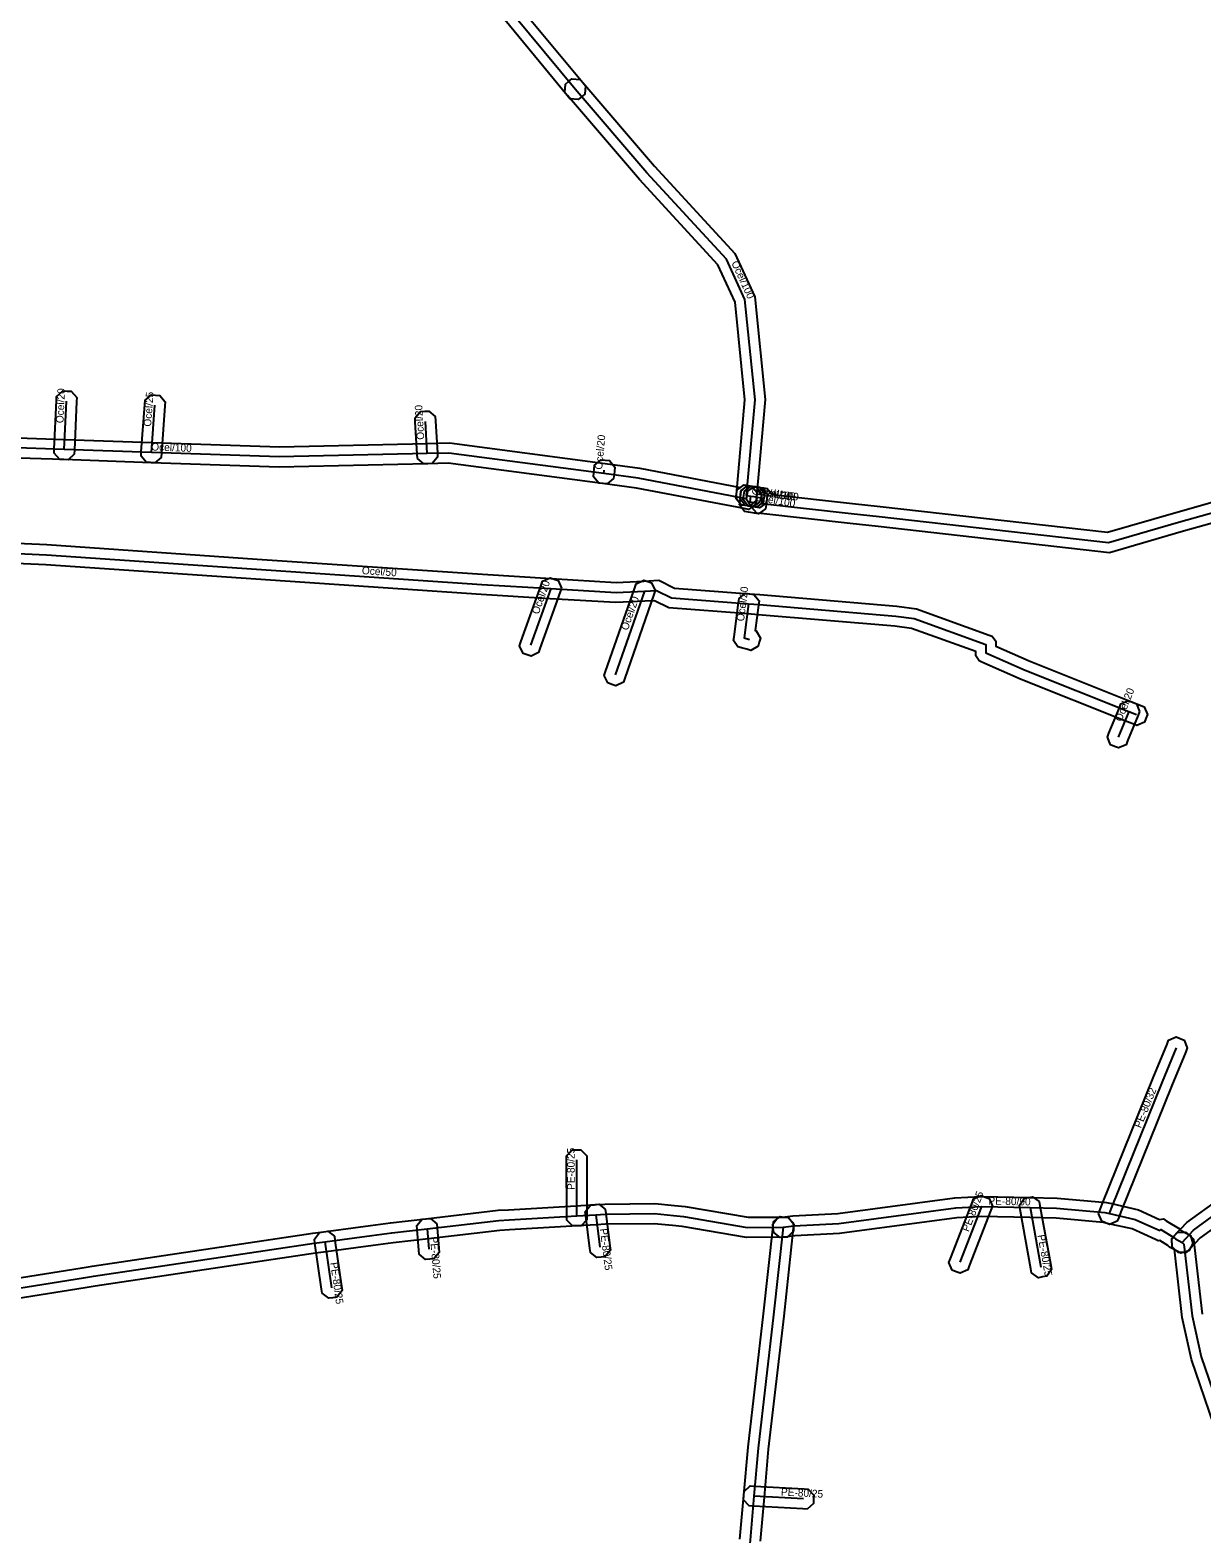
# Model space of a CAD drawing. Extents: x -569373 to -565022, y -1135090 to -1131496.
# Drawn here: x -565803.8 to -565687.7, y -1133883.9 to -1133734.9 of the extents above; entities that cross this region are included whole.
import ezdxf

# ---------------------------------------------------------------- set-up
doc = ezdxf.new("R2010")
doc.units = 0
for name, color, linetype in [('1', 7, 'Continuous'), ('24', 7, 'Continuous'), ('30', 7, 'Continuous')]:
    doc.layers.add(name, color=color, linetype=linetype)

msp = doc.modelspace()

# ---------------------------------------------------------------- linework, layer by layer
at = {"layer": '1'}
for points in [[(-565755.962, -1133731.747), (-565749.03, -1133740.122), (-565748.766, -1133740.441), (-565748.843, -1133741.266), (-565749.162, -1133741.53), (-565749.481, -1133741.794), (-565750.306, -1133741.717), (-565750.57, -1133741.398), (-565758.16, -1133732.228)], [(-565805.939, -1133775.27), (-565800.346, -1133775.461), (-565791.726, -1133775.761), (-565779.084, -1133776.19), (-565764.463, -1133775.86), (-565762.246, -1133775.808), (-565746.809, -1133777.839), (-565743.39, -1133778.292), (-565733.424, -1133780.205), (-565733.117, -1133779.967), (-565732.706, -1133780.018), (-565732.295, -1133780.069), (-565731.787, -1133780.723), (-565731.838, -1133781.134), (-565731.878, -1133781.454), (-565731.931, -1133781.884), (-565732.282, -1133782.139), (-565732.633, -1133782.394), (-565733.059, -1133782.312), (-565743.71, -1133780.268), (-565747.071, -1133779.821), (-565762.354, -1133777.812), (-565764.417, -1133777.86), (-565779.096, -1133778.19), (-565791.794, -1133777.759), (-565800.414, -1133777.459), (-565806.001, -1133777.27)], [(-565683.638, -1133782.882), (-565689.775, -1133784.611), (-565696.894, -1133786.676), (-565719.8, -1133784.084), (-565722.56, -1133783.784), (-565731.421, -1133782.794), (-565731.801, -1133782.751), (-565732.31, -1133782.182), (-565732.31, -1133782.097), (-565732.363, -1133782.088), (-565732.844, -1133781.414), (-565732.776, -1133781.006), (-565732.708, -1133780.597), (-565732.034, -1133780.116), (-565731.626, -1133780.184), (-565731.146, -1133780.264), (-565730.784, -1133780.324), (-565730.31, -1133780.883), (-565730.31, -1133780.905), (-565722.34, -1133781.796), (-565719.58, -1133782.096), (-565697.066, -1133784.644), (-565690.325, -1133782.689), (-565684.182, -1133780.958)], [(-565821.436, -1133785.008), (-565802.103, -1133785.872), (-565781.272, -1133787.302), (-565758.965, -1133788.812), (-565752.159, -1133789.232), (-565745.745, -1133789.618), (-565742.99, -1133789.481), (-565741.519, -1133789.408), (-565739.97, -1133790.178), (-565732.554, -1133790.743), (-565731.5, -1133790.823), (-565717.934, -1133791.975), (-565716.004, -1133792.222), (-565708.79, -1133794.83), (-565708.496, -1133794.936), (-565708.134, -1133795.445), (-565708.13, -1133795.758), (-565708.128, -1133795.937), (-565704.842, -1133797.398), (-565694.61, -1133801.471), (-565693.831, -1133801.781), (-565693.446, -1133801.934), (-565693.118, -1133802.694), (-565693.271, -1133803.079), (-565693.424, -1133803.464), (-565694.184, -1133803.792), (-565694.569, -1133803.639), (-565695.35, -1133803.329), (-565705.618, -1133799.242), (-565709.526, -1133797.504), (-565709.794, -1133797.385), (-565710.116, -1133796.895), (-565710.12, -1133796.602), (-565710.121, -1133796.475), (-565716.476, -1133794.178), (-565718.146, -1133793.965), (-565731.66, -1133792.817), (-565732.706, -1133792.737), (-565740.51, -1133792.142), (-565741.941, -1133791.432), (-565742.89, -1133791.479), (-565745.755, -1133791.622), (-565752.281, -1133791.228), (-565759.095, -1133790.808), (-565781.408, -1133789.298), (-565802.217, -1133787.868), (-565821.404, -1133787.012)], [(-565684.684, -1133852.193), (-565687.896, -1133854.514), (-565688.969, -1133855.663), (-565689.252, -1133855.965), (-565690.08, -1133855.993), (-565690.383, -1133855.711), (-565690.685, -1133855.428), (-565690.713, -1133854.6), (-565690.431, -1133854.297), (-565689.224, -1133853.006), (-565686.016, -1133850.687)], [(-565810.668, -1133859.412), (-565798.624, -1133857.492), (-565797.629, -1133857.341), (-565775.779, -1133854.08), (-565774.701, -1133853.939), (-565770.052, -1133853.315), (-565768.065, -1133853.048), (-565764.566, -1133852.637), (-565757.428, -1133851.803), (-565756.399, -1133851.742), (-565749.688, -1133851.352), (-565747.811, -1133851.242), (-565746.857, -1133851.18), (-565741.893, -1133851.129), (-565739.947, -1133851.331), (-565738.915, -1133851.439), (-565732.669, -1133852.49), (-565729.196, -1133852.47), (-565728.782, -1133852.468), (-565728.192, -1133853.05), (-565728.19, -1133853.464), (-565728.188, -1133853.878), (-565728.77, -1133854.468), (-565729.184, -1133854.47), (-565732.831, -1133854.49), (-565739.185, -1133853.421), (-565740.153, -1133853.321), (-565741.987, -1133853.131), (-565746.783, -1133853.18), (-565747.689, -1133853.238), (-565749.572, -1133853.348), (-565756.281, -1133853.738), (-565757.252, -1133853.797), (-565764.334, -1133854.623), (-565767.815, -1133855.032), (-565769.786, -1133855.297), (-565774.439, -1133855.921), (-565775.501, -1133856.06), (-565797.331, -1133859.319), (-565798.316, -1133859.468), (-565810.352, -1133861.388)], [(-565733.476, -1133884.381), (-565733.086, -1133880.021), (-565732.665, -1133875.268), (-565731.134, -1133862.058), (-565730.184, -1133853.361), (-565730.139, -1133852.949), (-565729.493, -1133852.431), (-565729.081, -1133852.476), (-565728.669, -1133852.521), (-565728.151, -1133853.167), (-565728.196, -1133853.579), (-565729.146, -1133862.282), (-565730.675, -1133875.472), (-565731.094, -1133880.199), (-565731.484, -1133884.559)], [(-565685.698, -1133875.567), (-565688.754, -1133866.571), (-565689.687, -1133862.427), (-565690.461, -1133855.641), (-565690.676, -1133855.449), (-565690.721, -1133854.622), (-565690.445, -1133854.313), (-565690.169, -1133854.004), (-565689.342, -1133853.959), (-565689.033, -1133854.235), (-565688.56, -1133854.659), (-565687.713, -1133862.093)]]:
    msp.add_lwpolyline(points, dxfattribs=at)
for points in [[(-565733.863, -1133781.334), (-565733.826, -1133780.921), (-565732.985, -1133771.526), (-565733.958, -1133761.865), (-565735.653, -1133758.151), (-565743.437, -1133749.715), (-565750.559, -1133741.411), (-565750.829, -1133741.097), (-565750.765, -1133740.271), (-565750.451, -1133740.001), (-565750.137, -1133739.731), (-565749.311, -1133739.795), (-565749.041, -1133740.109), (-565741.943, -1133748.385), (-565733.967, -1133757.029), (-565732.002, -1133761.335), (-565730.975, -1133771.514), (-565731.834, -1133781.099), (-565731.871, -1133781.512), (-565732.506, -1133782.043), (-565732.919, -1133782.006), (-565733.332, -1133781.969)], [(-565801.398, -1133776.828), (-565801.379, -1133776.414), (-565801.159, -1133771.614), (-565801.14, -1133771.2), (-565800.528, -1133770.642), (-565800.114, -1133770.661), (-565799.7, -1133770.68), (-565799.142, -1133771.292), (-565799.161, -1133771.706), (-565799.381, -1133776.506), (-565799.4, -1133776.92), (-565800.012, -1133777.478), (-565800.426, -1133777.459), (-565800.84, -1133777.44)], [(-565792.787, -1133777.101), (-565792.757, -1133776.688), (-565792.417, -1133771.988), (-565792.387, -1133771.575), (-565791.761, -1133771.033), (-565791.348, -1133771.063), (-565790.935, -1133771.093), (-565790.393, -1133771.719), (-565790.423, -1133772.132), (-565790.763, -1133776.832), (-565790.793, -1133777.245), (-565791.419, -1133777.787), (-565791.832, -1133777.757), (-565792.245, -1133777.727)], [(-565765.414, -1133777.333), (-565765.438, -1133776.919), (-565765.628, -1133773.729), (-565765.653, -1133773.316), (-565765.103, -1133772.696), (-565764.689, -1133772.672), (-565764.276, -1133772.647), (-565763.656, -1133773.197), (-565763.632, -1133773.611), (-565763.442, -1133776.801), (-565763.417, -1133777.214), (-565763.967, -1133777.834), (-565764.381, -1133777.858), (-565764.794, -1133777.883)], [(-565747.975, -1133779.149), (-565747.936, -1133778.737), (-565747.906, -1133778.417), (-565747.867, -1133778.004), (-565747.229, -1133777.475), (-565746.817, -1133777.514), (-565746.404, -1133777.553), (-565745.875, -1133778.191), (-565745.914, -1133778.603), (-565745.944, -1133778.923), (-565745.983, -1133779.336), (-565746.621, -1133779.865), (-565747.033, -1133779.826), (-565747.446, -1133779.787)], [(-565733.074, -1133779.956), (-565732.666, -1133780.024), (-565732.246, -1133780.094), (-565731.837, -1133780.162), (-565731.356, -1133780.836), (-565731.424, -1133781.244), (-565731.492, -1133781.653), (-565732.166, -1133782.134), (-565732.574, -1133782.066), (-565732.994, -1133781.996), (-565733.403, -1133781.928), (-565733.884, -1133781.254), (-565733.816, -1133780.846), (-565733.748, -1133780.437)], [(-565731.92, -1133780.115), (-565731.896, -1133780.143), (-565731.642, -1133780.181), (-565731.232, -1133780.242), (-565730.74, -1133780.908), (-565730.801, -1133781.318), (-565730.891, -1133781.918), (-565730.953, -1133782.333), (-565731.293, -1133782.58), (-565731.633, -1133782.826), (-565732.047, -1133782.756), (-565732.637, -1133782.656), (-565733.032, -1133782.589), (-565733.511, -1133781.948), (-565733.463, -1133781.55), (-565733.425, -1133781.241), (-565733.407, -1133781.003), (-565733.375, -1133780.59), (-565732.746, -1133780.051), (-565732.333, -1133780.083)], [(-565732.676, -1133780.031), (-565732.266, -1133780.09), (-565731.956, -1133780.135), (-565731.546, -1133780.195), (-565731.051, -1133780.859), (-565731.11, -1133781.269), (-565731.17, -1133781.679), (-565731.834, -1133782.174), (-565732.244, -1133782.115), (-565732.554, -1133782.07), (-565732.964, -1133782.01), (-565733.459, -1133781.346), (-565733.4, -1133780.936), (-565733.34, -1133780.526)], [(-565732.366, -1133780.076), (-565731.956, -1133780.135), (-565731.646, -1133780.18), (-565731.236, -1133780.24), (-565730.741, -1133780.904), (-565730.8, -1133781.314), (-565730.86, -1133781.724), (-565731.524, -1133782.219), (-565731.934, -1133782.16), (-565732.244, -1133782.115), (-565732.654, -1133782.055), (-565733.149, -1133781.391), (-565733.09, -1133780.981), (-565733.03, -1133780.571)], [(-565751.139, -1133790.176), (-565751.278, -1133790.566), (-565753.278, -1133796.176), (-565753.417, -1133796.566), (-565754.166, -1133796.921), (-565754.556, -1133796.782), (-565754.946, -1133796.643), (-565755.301, -1133795.894), (-565755.162, -1133795.504), (-565753.162, -1133789.894), (-565753.023, -1133789.504), (-565752.274, -1133789.149), (-565751.884, -1133789.288), (-565751.494, -1133789.427)], [(-565741.86, -1133790.418), (-565741.996, -1133790.809), (-565744.886, -1133799.099), (-565745.022, -1133799.49), (-565745.768, -1133799.85), (-565746.159, -1133799.714), (-565746.55, -1133799.578), (-565746.91, -1133798.832), (-565746.774, -1133798.441), (-565743.884, -1133790.151), (-565743.748, -1133789.76), (-565743.002, -1133789.4), (-565742.611, -1133789.536), (-565742.22, -1133789.672)], [(-565731.638, -1133791.869), (-565731.966, -1133794.388), (-565731.863, -1133794.417), (-565731.455, -1133795.139), (-565731.566, -1133795.538), (-565731.677, -1133795.937), (-565732.399, -1133796.345), (-565732.798, -1133796.234), (-565733.338, -1133796.084), (-565733.698, -1133795.984), (-565734.11, -1133795.361), (-565734.062, -1133794.991), (-565733.622, -1133791.611), (-565733.569, -1133791.2), (-565732.912, -1133790.695), (-565732.501, -1133790.748), (-565732.09, -1133790.801), (-565731.585, -1133791.458)], [(-565693.898, -1133802.393), (-565694.054, -1133802.777), (-565695.084, -1133805.307), (-565695.24, -1133805.691), (-565696.003, -1133806.012), (-565696.387, -1133805.856), (-565696.771, -1133805.7), (-565697.092, -1133804.937), (-565696.936, -1133804.553), (-565695.906, -1133802.023), (-565695.75, -1133801.639), (-565694.987, -1133801.318), (-565694.603, -1133801.474), (-565694.219, -1133801.63)], [(-565697.973, -1133852.119), (-565697.814, -1133851.737), (-565697.596, -1133851.211), (-565692.547, -1133838.695), (-565691.187, -1133835.344), (-565691.031, -1133834.96), (-565690.268, -1133834.637), (-565689.884, -1133834.793), (-565689.5, -1133834.949), (-565689.177, -1133835.712), (-565689.333, -1133836.096), (-565690.693, -1133839.445), (-565695.744, -1133851.969), (-565695.966, -1133852.503), (-565696.125, -1133852.886), (-565696.891, -1133853.203), (-565697.273, -1133853.044), (-565697.656, -1133852.885)], [(-565750.629, -1133852.766), (-565750.63, -1133852.352), (-565750.64, -1133846.822), (-565750.641, -1133846.408), (-565750.056, -1133845.821), (-565749.642, -1133845.82), (-565749.228, -1133845.819), (-565748.641, -1133846.404), (-565748.64, -1133846.818), (-565748.63, -1133852.348), (-565748.629, -1133852.762), (-565749.214, -1133853.349), (-565749.628, -1133853.35), (-565750.042, -1133853.351)], [(-565704.773, -1133852.53), (-565709.563, -1133852.42), (-565711.996, -1133852.556), (-565723.607, -1133854.106), (-565728.056, -1133854.347), (-565729.076, -1133854.464), (-565729.488, -1133854.511), (-565730.137, -1133853.995), (-565730.184, -1133853.584), (-565730.231, -1133853.172), (-565729.715, -1133852.523), (-565729.304, -1133852.476), (-565728.224, -1133852.353), (-565723.793, -1133852.114), (-565712.184, -1133850.564), (-565709.608, -1133850.42), (-565709.549, -1133850.42), (-565704.727, -1133850.53), (-565702.064, -1133850.591), (-565697.174, -1133851.03), (-565696.669, -1133851.145), (-565694.009, -1133851.747), (-565691.919, -1133852.698), (-565691.55, -1133852.663), (-565691.265, -1133852.839), (-565689.9, -1133853.681), (-565689.77, -1133853.803), (-565689.221, -1133854.102), (-565688.857, -1133854.3), (-565688.624, -1133855.095), (-565688.822, -1133855.459), (-565689.02, -1133855.823), (-565689.815, -1133856.056), (-565690.179, -1133855.858), (-565690.95, -1133855.437), (-565691.12, -1133855.279), (-565691.882, -1133854.808), (-565692.05, -1133854.835), (-565692.324, -1133854.71), (-565694.651, -1133853.653), (-565697.111, -1133853.095), (-565697.486, -1133853.01), (-565702.176, -1133852.589)], [(-565708.477, -1133851.395), (-565708.627, -1133851.781), (-565710.767, -1133857.311), (-565710.917, -1133857.697), (-565711.675, -1133858.033), (-565712.061, -1133857.883), (-565712.447, -1133857.733), (-565712.783, -1133856.975), (-565712.633, -1133856.589), (-565710.493, -1133851.059), (-565710.343, -1133850.673), (-565709.585, -1133850.337), (-565709.199, -1133850.487), (-565708.813, -1133850.637)], [(-565703.84, -1133850.943), (-565703.766, -1133851.351), (-565702.696, -1133857.241), (-565702.622, -1133857.649), (-565703.093, -1133858.33), (-565703.501, -1133858.404), (-565703.909, -1133858.478), (-565704.59, -1133858.007), (-565704.664, -1133857.599), (-565705.734, -1133851.709), (-565705.808, -1133851.301), (-565705.337, -1133850.62), (-565704.929, -1133850.546), (-565704.521, -1133850.472)], [(-565746.809, -1133851.705), (-565746.758, -1133852.116), (-565746.358, -1133855.326), (-565746.307, -1133855.737), (-565746.815, -1133856.391), (-565747.226, -1133856.442), (-565747.637, -1133856.493), (-565748.291, -1133855.985), (-565748.342, -1133855.574), (-565748.742, -1133852.364), (-565748.793, -1133851.953), (-565748.285, -1133851.299), (-565747.874, -1133851.248), (-565747.463, -1133851.197)], [(-565763.488, -1133853.133), (-565763.454, -1133853.546), (-565763.284, -1133855.566), (-565763.249, -1133855.979), (-565763.783, -1133856.612), (-565764.196, -1133856.646), (-565764.609, -1133856.681), (-565765.242, -1133856.147), (-565765.276, -1133855.734), (-565765.446, -1133853.714), (-565765.481, -1133853.301), (-565764.947, -1133852.668), (-565764.534, -1133852.634), (-565764.121, -1133852.599)], [(-565773.638, -1133854.38), (-565773.58, -1133854.79), (-565772.94, -1133859.33), (-565772.882, -1133859.74), (-565773.38, -1133860.402), (-565773.79, -1133860.46), (-565774.2, -1133860.518), (-565774.862, -1133860.02), (-565774.92, -1133859.61), (-565775.56, -1133855.07), (-565775.618, -1133854.66), (-565775.12, -1133853.998), (-565774.71, -1133853.94), (-565774.3, -1133853.882)], [(-565726.821, -1133881.401), (-565727.235, -1133881.378), (-565732.145, -1133881.108), (-565732.558, -1133881.086), (-565733.111, -1133880.469), (-565733.088, -1133880.055), (-565733.066, -1133879.642), (-565732.449, -1133879.089), (-565732.035, -1133879.112), (-565727.125, -1133879.382), (-565726.712, -1133879.404), (-565726.159, -1133880.021), (-565726.182, -1133880.435), (-565726.204, -1133880.848)]]:
    msp.add_lwpolyline(points, close=True, dxfattribs=at)
at = {"layer": '24'}
for points in [[(-565749.8, -1133740.76), (-565757.39, -1133731.59), (-565753.04, -1133728.21), (-565757.57, -1133717.97), (-565761.42, -1133709.27), (-565765.12, -1133697), (-565767.29, -1133689.8), (-565770.57, -1133673.93), (-565771.29, -1133668.81), (-565774.1, -1133648.7), (-565774.91, -1133640.21)], [(-565732.83, -1133781.01), (-565731.98, -1133771.52), (-565732.98, -1133761.6), (-565734.81, -1133757.59), (-565742.69, -1133749.05), (-565749.8, -1133740.76)], [(-565800.38, -1133776.46), (-565800.16, -1133771.66)], [(-565731.79, -1133781.17), (-565731.31, -1133781.25), (-565731.31, -1133781.8), (-565722.45, -1133782.79), (-565719.69, -1133783.09), (-565696.98, -1133785.66), (-565690.05, -1133783.65), (-565683.91, -1133781.92), (-565674.33, -1133779.21), (-565666.38, -1133776.92), (-565664.06, -1133776.24), (-565646.12, -1133770.95), (-565644.96, -1133770.62), (-565644.79, -1133770.7), (-565643.12, -1133776.29), (-565639.22, -1133790.9), (-565637.82, -1133792.15), (-565630.96, -1133797.98), (-565630.6, -1133798.24), (-565626.94, -1133796.32), (-565610.38, -1133787.45)], [(-565791.76, -1133776.76), (-565791.42, -1133772.06)], [(-565764.44, -1133776.86), (-565764.63, -1133773.67)], [(-565732.83, -1133781.01), (-565732.87, -1133781.33), (-565743.55, -1133779.28), (-565746.94, -1133778.83), (-565762.3, -1133776.81), (-565764.44, -1133776.86), (-565779.09, -1133777.19), (-565791.76, -1133776.76), (-565800.38, -1133776.46), (-565805.97, -1133776.27), (-565827.93, -1133775.65), (-565851.65, -1133776.72)], [(-565746.94, -1133778.83), (-565746.91, -1133778.51)], [(-565732.83, -1133781.01), (-565732.41, -1133781.08)], [(-565731.79, -1133781.17), (-565731.88, -1133781.77), (-565732.47, -1133781.67), (-565732.43, -1133781.34), (-565732.41, -1133781.08)], [(-565732.41, -1133781.08), (-565732.1, -1133781.125)], [(-565732.1, -1133781.125), (-565731.79, -1133781.17)], [(-565850.78, -1133788.29), (-565821.42, -1133786.01), (-565802.16, -1133786.87), (-565781.34, -1133788.3), (-565759.03, -1133789.81), (-565752.22, -1133790.23), (-565745.75, -1133790.62), (-565742.94, -1133790.48), (-565741.73, -1133790.42), (-565740.24, -1133791.16), (-565732.63, -1133791.74), (-565731.58, -1133791.82), (-565718.04, -1133792.97), (-565716.24, -1133793.2), (-565709.13, -1133795.77), (-565709.12, -1133796.59), (-565705.23, -1133798.32), (-565694.98, -1133802.4), (-565694.2, -1133802.71)], [(-565752.22, -1133790.23), (-565754.22, -1133795.84)], [(-565742.94, -1133790.48), (-565745.83, -1133798.77)], [(-565732.63, -1133791.74), (-565733.07, -1133795.12), (-565732.53, -1133795.27)], [(-565694.98, -1133802.4), (-565696.01, -1133804.93)], [(-565689.7, -1133854.98), (-565688.56, -1133853.76), (-565685.35, -1133851.44), (-565682.29, -1133848.14), (-565672.318, -1133835.092), (-565671.59, -1133834.14), (-565658.14, -1133816.52), (-565652.84, -1133820.6), (-565648.38, -1133824.67), (-565641.15, -1133832.74), (-565629.21, -1133848.21), (-565623.69, -1133855.25)], [(-565696.89, -1133852.12), (-565696.67, -1133851.59), (-565691.62, -1133839.07), (-565690.26, -1133835.72)], [(-565749.63, -1133852.35), (-565749.64, -1133846.82)], [(-565810.51, -1133860.4), (-565798.47, -1133858.48), (-565797.48, -1133858.33), (-565775.64, -1133855.07), (-565774.57, -1133854.93), (-565769.919, -1133854.306), (-565767.94, -1133854.04), (-565764.45, -1133853.63), (-565757.34, -1133852.8), (-565756.34, -1133852.74), (-565749.63, -1133852.35), (-565747.75, -1133852.24), (-565746.82, -1133852.18), (-565741.94, -1133852.13), (-565740.05, -1133852.326), (-565739.05, -1133852.43), (-565732.75, -1133853.49), (-565729.19, -1133853.47)], [(-565747.75, -1133852.24), (-565747.35, -1133855.45)], [(-565729.19, -1133853.47), (-565728.14, -1133853.35), (-565723.7, -1133853.11), (-565712.09, -1133851.56), (-565709.58, -1133851.42), (-565709.56, -1133851.42), (-565704.75, -1133851.53), (-565702.12, -1133851.59), (-565697.33, -1133852.02), (-565696.89, -1133852.12), (-565694.33, -1133852.7), (-565691.91, -1133853.8), (-565691.79, -1133853.69), (-565690.51, -1133854.48), (-565690.36, -1133854.62), (-565689.7, -1133854.98)], [(-565709.56, -1133851.42), (-565711.7, -1133856.95)], [(-565704.75, -1133851.53), (-565703.68, -1133857.42)], [(-565764.45, -1133853.63), (-565764.28, -1133855.65)], [(-565729.19, -1133853.47), (-565730.14, -1133862.17), (-565731.67, -1133875.37), (-565732.09, -1133880.11), (-565732.48, -1133884.47), (-565732.57, -1133885.47), (-565733.41, -1133893.71), (-565734.72, -1133903.27), (-565734.843, -1133904.26), (-565735.83, -1133912.17), (-565735.96, -1133913.216), (-565736.393, -1133916.667), (-565737.33, -1133926.25), (-565737.447, -1133927.24), (-565737.62, -1133928.71)], [(-565774.57, -1133854.93), (-565773.93, -1133859.47)], [(-565689.7, -1133854.98), (-565689.51, -1133855.15), (-565688.7, -1133862.26), (-565687.79, -1133866.3), (-565684.75, -1133875.25)], [(-565727.18, -1133880.38), (-565732.09, -1133880.11)]]:
    msp.add_lwpolyline(points, dxfattribs=at)

# ---------------------------------------------------------------- texts
at = {"layer": '30'}
for s, rotation, p in [('Ocel/100', 294.53002, (-565734.347, -1133757.965)), ('Ocel/20', 87.37578, (-565800.47, -1133773.86)), ('Ocel/25', 85.86241, (-565791.79, -1133774.21)), ('Ocel/20', 93.40857, (-565764.735, -1133775.465)), ('Ocel/100', 358.00675, (-565791.785, -1133776.552)), ('Ocel/20', 84.64417, (-565747.125, -1133778.47)), ('Ocel/100', 350.53768, (-565732.371, -1133780.853)), ('Ocel/100', 351.74056, (-565732.006, -1133780.91)), ('Ocel/100', 351.74056, (-565731.696, -1133780.955)), ('Ocel/100', 350.38027, (-565732.018, -1133781.513)), ('Ocel/50', 356.12797, (-565770.936, -1133788.791)), ('Ocel/20', 70.37853, (-565753.42, -1133792.835)), ('Ocel/20', 70.78079, (-565744.585, -1133794.425)), ('Ocel/20', 82.58309, (-565733.086, -1133793.508)), ('Ocel/20', 67.84804, (-565695.695, -1133803.465)), ('PE-80/32', 68.03309, (-565693.776, -1133843.72)), ('PE-80/25', 90.10361, (-565749.835, -1133849.785)), ('PE-80/25', 68.84455, (-565710.83, -1133853.985)), ('PE-80/90', 358.68993, (-565708.88, -1133851.231)), ('PE-80/25', 277.10305, (-565747.35, -1133853.645)), ('PE-80/25', 274.81059, (-565764.165, -1133854.44)), ('PE-80/25', 280.29629, (-565704.015, -1133854.275)), ('PE-80/25', 278.02406, (-565774.05, -1133857)), ('PE-80/25', 356.85249, (-565729.435, -1133880.045))]:
    msp.add_text(s, height=0.75, rotation=rotation, dxfattribs=at).set_placement(p)

doc.saveas('drawing.dxf')
